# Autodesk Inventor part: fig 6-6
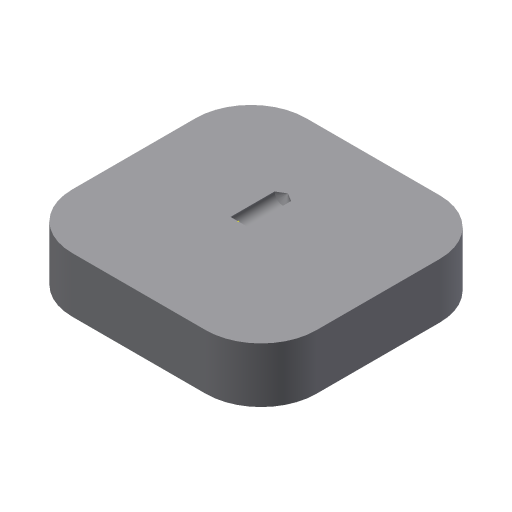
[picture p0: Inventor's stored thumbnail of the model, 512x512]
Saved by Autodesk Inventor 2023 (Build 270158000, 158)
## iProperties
Created: 2004-05
Part Number: fig 6-6
Document SubType Name: Modeling
Designer: CADCIM Technologies
Manufacturer: Standard
Standards Organization: Custom
Density: 1 g/cm^3
Material: Generic
Appearance: Default
Author: CADCIM Technologies
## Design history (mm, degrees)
sketch "Sketch1"
  geometry: L1 (0, 0)-(44.293, 0); L2 (44.293, 0)-(44.293, 42.442); L3 (44.293, 42.442)-(0, 42.442); L4 (0, 42.442)-(0, 0)
  constraints: 8 end point, 2 parallel, 1 horizontal, 1 perpendicular
extrude "Extrusion1" new body sketch "Sketch1" distance "d0" = 10; taper "d1" = 0 deg
fillet "Fillet1" dims "d2" = 10
sketch "Sketch2"
  geometry: 1 further point
sketch "Sketch3"
  geometry: L1 (10, 42.442)-(34.293, 42.442) reference; L2 (0, 10)-(0, 32.442) reference; L3 (34.293, 0)-(10, 0) reference; L4 (44.293, 32.442)-(44.293, 10) reference; A1 r 10 centre (34.293, 32.442) between (44.293, 32.442) and (34.293, 42.442) reference; A2 r 10 centre (10, 32.442) between (10, 42.442) and (0, 32.442) reference; A3 r 10 centre (10, 10) between (0, 10) and (10, 0) reference; A4 r 10 centre (34.293, 10) between (34.293, 0) and (44.293, 10) reference; 1 further point
workpoint "Work Point1"
hole "Hole4" diameter "d33" = 3; stored, may be unused: countersink angle "d37" = 90 deg, drill point angle "d39" = 118 deg; dims "d31" = 10, "d32" = 10, "d34" = 6, "d35" = 4, "d36" = 2, "d38" = 8
body "Solid1"
